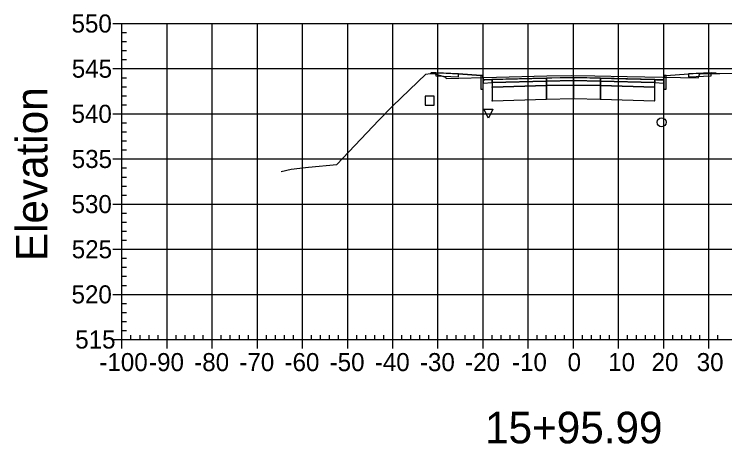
# Model space of a CAD drawing. Extents: x 704834 to 709892, y 372981 to 377533.
# Drawn here: x 706906 to 707063.4, y 376297.7 to 376392.9 of the extents above; entities that cross this region are included whole.
import ezdxf

# ---------------------------------------------------------------- set-up
doc = ezdxf.new("R2010")
doc.units = 0
for name, color, linetype in [('1', 7, 'Continuous'), ('10', 7, 'Continuous'), ('13', 7, 'Continuous'), ('14', 7, 'Continuous'), ('57', 7, 'Continuous'), ('60', 7, 'Continuous'), ('Default_Xsect', 7, 'Continuous'), ('Existing', 7, 'Continuous')]:
    doc.layers.add(name, color=color, linetype=linetype)

msp = doc.modelspace()

# ---------------------------------------------------------------- linework, layer by layer
for points in [[(706998.42, 376379.87), (706998.28, 376379.73)], [(706999.42, 376379.91), (706998.42, 376379.87)], [(707009.42, 376379.31), (707004.42, 376379.71)], [(707050.42, 376379.31), (707055.42, 376379.71)], [(707060.42, 376379.91), (707061.42, 376379.87)], [(707061.42, 376379.87), (707061.55, 376379.73)]]:
    msp.add_lwpolyline(points)
for points in [[(707004.42, 376379.71), (706999.42, 376379.91), (706999.42, 376379.25), (707004.42, 376379.04)], [(707009.92, 376378.31), (707009.83, 376379.31), (707009.42, 376379.31), (707009.42, 376376.31), (707009.92, 376376.31)], [(707023.92, 376378.75), (707011.92, 376378.39), (707011.92, 376377.72), (707023.92, 376378.08)], [(707029.92, 376378.87), (707023.92, 376378.75), (707023.92, 376378.08), (707029.92, 376378.2)], [(707029.92, 376378.2), (707035.92, 376378.08), (707035.92, 376378.75), (707029.92, 376378.87)], [(707035.92, 376378.08), (707047.92, 376377.72), (707047.92, 376378.39), (707035.92, 376378.75)], [(707049.92, 376376.31), (707050.42, 376376.31), (707050.42, 376379.31), (707050, 376379.31), (707049.92, 376378.31)], [(707055.42, 376379.04), (707060.42, 376379.24), (707060.42, 376379.91), (707055.42, 376379.71)], [(707011.92, 376378.39), (707009.92, 376378.31), (707009.92, 376377.64), (707011.92, 376377.72)], [(707023.92, 376378.08), (707011.92, 376377.72), (707011.92, 376376.72), (707023.92, 376377.08)], [(707023.92, 376377.08), (707011.92, 376376.72), (707011.92, 376373.72), (707023.92, 376374.08)], [(707023.87, 376378.03), (707023.97, 376378.03), (707023.97, 376378.13), (707023.87, 376378.13)], [(707023.87, 376377.03), (707023.97, 376377.03), (707023.97, 376377.13), (707023.87, 376377.13)], [(707029.92, 376378.2), (707023.92, 376378.08), (707023.92, 376377.08), (707029.92, 376377.2)], [(707029.92, 376377.2), (707023.92, 376377.08), (707023.92, 376374.08), (707029.92, 376374.2)], [(707029.87, 376378.15), (707029.97, 376378.15), (707029.97, 376378.25), (707029.87, 376378.25)], [(707029.87, 376377.15), (707029.97, 376377.15), (707029.97, 376377.25), (707029.87, 376377.25)], [(707029.92, 376377.2), (707035.92, 376377.08), (707035.92, 376378.08), (707029.92, 376378.2)], [(707029.92, 376374.2), (707035.92, 376374.08), (707035.92, 376377.08), (707029.92, 376377.2)], [(707035.87, 376378.03), (707035.97, 376378.03), (707035.97, 376378.13), (707035.87, 376378.13)], [(707035.87, 376377.03), (707035.97, 376377.03), (707035.97, 376377.13), (707035.87, 376377.13)], [(707035.92, 376377.08), (707047.92, 376376.72), (707047.92, 376377.72), (707035.92, 376378.08)], [(707035.92, 376374.08), (707047.92, 376373.72), (707047.92, 376376.72), (707035.92, 376377.08)], [(707047.92, 376377.72), (707049.92, 376377.64), (707049.92, 376378.31), (707047.92, 376378.39)], [(707011.87, 376376.67), (707011.97, 376376.67), (707011.97, 376376.77), (707011.87, 376376.77)], [(707047.87, 376376.67), (707047.97, 376376.67), (707047.97, 376376.77), (707047.87, 376376.77)], [(707011.87, 376373.67), (707011.97, 376373.67), (707011.97, 376373.77), (707011.87, 376373.77)], [(707023.87, 376374.03), (707023.97, 376374.03), (707023.97, 376374.13), (707023.87, 376374.13)], [(707029.87, 376374.15), (707029.97, 376374.15), (707029.97, 376374.25), (707029.87, 376374.25)], [(707035.87, 376374.03), (707035.97, 376374.03), (707035.97, 376374.13), (707035.87, 376374.13)], [(707047.87, 376373.67), (707047.97, 376373.67), (707047.97, 376373.77), (707047.87, 376373.77)]]:
    msp.add_lwpolyline(points, close=True)
at = {"layer": '1'}
msp.add_lwpolyline([(707011.09, 376369.88), (707010.09, 376371.88), (707012.09, 376371.88)], close=True, dxfattribs=at)
at = {"layer": '10'}
msp.add_lwpolyline([(706997.04, 376372.71), (706999.04, 376372.71), (706999.04, 376374.71), (706997.04, 376374.71)], close=True, dxfattribs=at)
at = {"layer": '13'}
msp.add_circle((707049.43, 376368.94), 1, dxfattribs=at)
at = {"layer": '14'}
for points in [[(706998.28, 376379.73), (706998.28, 376379.78), (706998.28, 376379.73), (706998.23, 376379.73), (706998.28, 376379.73), (706998.28, 376379.68), (706998.28, 376379.73), (706998.33, 376379.73)], [(707029.92, 376378.87), (707029.92, 376378.92), (707029.92, 376378.87), (707029.87, 376378.87), (707029.92, 376378.87), (707029.92, 376378.82), (707029.92, 376378.87), (707029.97, 376378.87)], [(707061.55, 376379.73), (707061.55, 376379.78), (707061.55, 376379.73), (707061.5, 376379.73), (707061.55, 376379.73), (707061.55, 376379.68), (707061.55, 376379.73), (707061.6, 376379.73)], [(707011.92, 376378.39), (707011.92, 376378.44), (707011.92, 376378.39), (707011.87, 376378.39), (707011.92, 376378.39), (707011.92, 376378.34), (707011.92, 376378.39), (707011.97, 376378.39)], [(707047.92, 376378.39), (707047.92, 376378.44), (707047.92, 376378.39), (707047.87, 376378.39), (707047.92, 376378.39), (707047.92, 376378.34), (707047.92, 376378.39), (707047.97, 376378.39)]]:
    msp.add_lwpolyline(points, dxfattribs=at)
at = {"layer": '57'}
for p, q in [((706927.91, 376390.82), (706929.91, 376390.82)), ((706929.91, 376390.82), (707129.91, 376390.82)), ((706929.91, 376320.82), (706929.91, 376390.82)), ((706929.91, 376320.82), (706929.91, 376390.82)), ((706939.91, 376320.82), (706939.91, 376390.82)), ((706949.91, 376320.82), (706949.91, 376390.82)), ((706959.91, 376320.82), (706959.91, 376390.82)), ((706969.91, 376320.82), (706969.91, 376390.82)), ((706979.91, 376320.82), (706979.91, 376390.82)), ((706989.91, 376320.82), (706989.91, 376390.82)), ((706999.91, 376320.82), (706999.91, 376390.82)), ((707009.91, 376320.82), (707009.91, 376390.82)), ((707019.91, 376320.82), (707019.91, 376390.82)), ((707029.91, 376320.82), (707029.91, 376390.82)), ((707039.91, 376320.82), (707039.91, 376390.82)), ((707049.91, 376320.82), (707049.91, 376390.82)), ((707059.91, 376320.82), (707059.91, 376390.82)), ((706929.91, 376388.82), (706930.91, 376388.82)), ((706929.91, 376386.82), (706930.91, 376386.82)), ((706929.91, 376384.82), (706930.91, 376384.82)), ((706929.91, 376382.82), (706930.91, 376382.82)), ((706927.91, 376380.82), (706929.91, 376380.82)), ((706929.91, 376380.82), (707129.91, 376380.82)), ((706929.91, 376378.82), (706930.91, 376378.82)), ((706929.91, 376376.82), (706930.91, 376376.82)), ((706929.91, 376374.82), (706930.91, 376374.82)), ((706929.91, 376372.82), (706930.91, 376372.82)), ((706927.91, 376370.82), (706929.91, 376370.82)), ((706929.91, 376370.82), (707129.91, 376370.82)), ((706929.91, 376368.82), (706930.91, 376368.82)), ((706929.91, 376366.82), (706930.91, 376366.82)), ((706929.91, 376364.82), (706930.91, 376364.82)), ((706929.91, 376362.82), (706930.91, 376362.82)), ((706927.91, 376360.82), (706929.91, 376360.82)), ((706929.91, 376360.82), (707129.91, 376360.82)), ((706929.91, 376358.82), (706930.91, 376358.82)), ((706929.91, 376356.82), (706930.91, 376356.82)), ((706929.91, 376354.82), (706930.91, 376354.82)), ((706929.91, 376352.82), (706930.91, 376352.82)), ((706927.91, 376350.82), (706929.91, 376350.82)), ((706929.91, 376350.82), (707129.91, 376350.82)), ((706929.91, 376348.82), (706930.91, 376348.82)), ((706929.91, 376346.82), (706930.91, 376346.82)), ((706929.91, 376344.82), (706930.91, 376344.82)), ((706929.91, 376342.82), (706930.91, 376342.82)), ((706927.91, 376340.82), (706929.91, 376340.82)), ((706929.91, 376340.82), (707129.91, 376340.82)), ((706929.91, 376338.82), (706930.91, 376338.82)), ((706929.91, 376336.82), (706930.91, 376336.82)), ((706929.91, 376334.82), (706930.91, 376334.82)), ((706929.91, 376332.82), (706930.91, 376332.82)), ((706927.91, 376330.82), (706929.91, 376330.82)), ((706929.91, 376330.82), (707129.91, 376330.82)), ((706929.91, 376328.82), (706930.91, 376328.82)), ((706929.91, 376326.82), (706930.91, 376326.82)), ((706929.91, 376324.82), (706930.91, 376324.82)), ((706929.91, 376322.82), (706930.91, 376322.82)), ((706931.91, 376320.82), (706931.91, 376321.82)), ((706933.91, 376320.82), (706933.91, 376321.82)), ((706935.91, 376320.82), (706935.91, 376321.82)), ((706937.91, 376320.82), (706937.91, 376321.82)), ((706941.91, 376320.82), (706941.91, 376321.82)), ((706943.91, 376320.82), (706943.91, 376321.82)), ((706945.91, 376320.82), (706945.91, 376321.82)), ((706947.91, 376320.82), (706947.91, 376321.82)), ((706951.91, 376320.82), (706951.91, 376321.82)), ((706953.91, 376320.82), (706953.91, 376321.82)), ((706955.91, 376320.82), (706955.91, 376321.82)), ((706957.91, 376320.82), (706957.91, 376321.82)), ((706961.91, 376320.82), (706961.91, 376321.82)), ((706963.91, 376320.82), (706963.91, 376321.82)), ((706965.91, 376320.82), (706965.91, 376321.82)), ((706967.91, 376320.82), (706967.91, 376321.82)), ((706971.91, 376320.82), (706971.91, 376321.82)), ((706973.91, 376320.82), (706973.91, 376321.82)), ((706975.91, 376320.82), (706975.91, 376321.82)), ((706977.91, 376320.82), (706977.91, 376321.82)), ((706981.91, 376320.82), (706981.91, 376321.82)), ((706983.91, 376320.82), (706983.91, 376321.82)), ((706985.91, 376320.82), (706985.91, 376321.82)), ((706987.91, 376320.82), (706987.91, 376321.82)), ((706991.91, 376320.82), (706991.91, 376321.82)), ((706993.91, 376320.82), (706993.91, 376321.82)), ((706995.91, 376320.82), (706995.91, 376321.82)), ((706997.91, 376320.82), (706997.91, 376321.82)), ((707001.91, 376320.82), (707001.91, 376321.82)), ((707003.91, 376320.82), (707003.91, 376321.82)), ((707005.91, 376320.82), (707005.91, 376321.82)), ((707007.91, 376320.82), (707007.91, 376321.82)), ((707011.91, 376320.82), (707011.91, 376321.82)), ((707013.91, 376320.82), (707013.91, 376321.82)), ((707015.91, 376320.82), (707015.91, 376321.82)), ((707017.91, 376320.82), (707017.91, 376321.82)), ((707021.91, 376320.82), (707021.91, 376321.82)), ((707023.91, 376320.82), (707023.91, 376321.82)), ((707025.91, 376320.82), (707025.91, 376321.82)), ((707027.91, 376320.82), (707027.91, 376321.82)), ((707031.91, 376320.82), (707031.91, 376321.82)), ((707033.91, 376320.82), (707033.91, 376321.82)), ((707035.91, 376320.82), (707035.91, 376321.82)), ((707037.91, 376320.82), (707037.91, 376321.82)), ((707041.91, 376320.82), (707041.91, 376321.82)), ((707043.91, 376320.82), (707043.91, 376321.82)), ((707045.91, 376320.82), (707045.91, 376321.82)), ((707047.91, 376320.82), (707047.91, 376321.82)), ((707051.91, 376320.82), (707051.91, 376321.82)), ((707053.91, 376320.82), (707053.91, 376321.82)), ((707055.91, 376320.82), (707055.91, 376321.82)), ((707057.91, 376320.82), (707057.91, 376321.82)), ((707061.91, 376320.82), (707061.91, 376321.82)), ((706927.91, 376320.82), (706929.91, 376320.82)), ((706929.91, 376320.82), (707129.91, 376320.82)), ((706929.91, 376320.82), (707129.91, 376320.82)), ((706929.91, 376318.82), (706929.91, 376320.82)), ((706939.91, 376318.82), (706939.91, 376320.82)), ((706949.91, 376318.82), (706949.91, 376320.82)), ((706959.91, 376318.82), (706959.91, 376320.82)), ((706969.91, 376318.82), (706969.91, 376320.82)), ((706979.91, 376318.82), (706979.91, 376320.82)), ((706989.91, 376318.82), (706989.91, 376320.82)), ((706999.91, 376318.82), (706999.91, 376320.82)), ((707009.91, 376318.82), (707009.91, 376320.82)), ((707019.91, 376318.82), (707019.91, 376320.82)), ((707029.91, 376318.82), (707029.91, 376320.82)), ((707039.91, 376318.82), (707039.91, 376320.82)), ((707049.91, 376318.82), (707049.91, 376320.82)), ((707059.91, 376318.82), (707059.91, 376320.82))]:
    msp.add_line(p, q, dxfattribs=at)
at = {"layer": 'Default_Xsect'}
msp.add_lwpolyline([(706998.28, 376379.73), (706998.4, 376379.85), (706998.42, 376379.87), (706998.61, 376379.88), (706999.42, 376379.91), (707000.39, 376379.87), (707004.42, 376379.71), (707005.39, 376379.63), (707009.42, 376379.31), (707009.5, 376379.31), (707009.83, 376379.31), (707009.85, 376379.12), (707009.92, 376378.31), (707010.31, 376378.33), (707011.92, 376378.39), (707014.29, 376378.46), (707023.92, 376378.75), (707025.11, 376378.77), (707029.92, 376378.87), (707031.11, 376378.84), (707035.92, 376378.75), (707038.33, 376378.67), (707047.92, 376378.39), (707048.32, 376378.37), (707049.92, 376378.31), (707049.93, 376378.51), (707050, 376379.31), (707050.08, 376379.31), (707050.42, 376379.31), (707051.43, 376379.39), (707055.42, 376379.71), (707056.43, 376379.75), (707060.42, 376379.91), (707060.62, 376379.9), (707061.42, 376379.87), (707061.43, 376379.85), (707061.55, 376379.73)], dxfattribs=at)
at = {"layer": 'Existing'}
msp.add_lwpolyline([(706965.15, 376358.03), (706967.36, 376358.53), (706971.23, 376359), (706977.49, 376359.6), (706986.84, 376369.44), (706989.9, 376372.58), (706997.21, 376379.59), (706998.17, 376379.73), (706999.04, 376379.75), (707001.58, 376378.92), (707001.72, 376378.65), (707024.05, 376379.2), (707029.59, 376379.34), (707034.63, 376379.22), (707041.81, 376379.09), (707057.53, 376378.78), (707057.8, 376379.38), (707057.98, 376379.72), (707058.62, 376379.72), (707061.89, 376379.73), (707062.31, 376379.75), (707067.3, 376379.83)], dxfattribs=at)

# ---------------------------------------------------------------- texts
at = {"layer": '1'}
msp.add_text('15+95.99', height=7, dxfattribs=at).set_placement((707010.34, 376297.82))
at = {"layer": '14'}
for p in [(706999.38, 376379.86), (706999.38, 376379.2), (707004.38, 376378.99), (707055.38, 376378.99), (707060.38, 376379.86), (707060.38, 376379.19)]:
    msp.add_text('+', height=0.1, dxfattribs=at).set_placement(p)
at = {"layer": '57'}
for s, p in [('550', (706918.74, 376388.82)), ('545', (706918.79, 376378.82)), ('540', (706918.74, 376368.82)), ('535', (706918.79, 376358.82)), ('530', (706918.74, 376348.82)), ('525', (706918.79, 376338.82)), ('520', (706918.74, 376328.82)), ('515', (706919.56, 376318.82)), ('-100', (706924.9, 376313.82)), ('-90', (706935.91, 376313.82)), ('-80', (706945.91, 376313.82)), ('-70', (706955.91, 376313.82)), ('-60', (706965.91, 376313.82)), ('-50', (706975.91, 376313.82)), ('-40', (706985.91, 376313.82)), ('-30', (706995.91, 376313.82)), ('-20', (707005.91, 376313.82)), ('-10', (707016.3, 376313.82)), ('0', (707028.62, 376313.82)), ('10', (707037.61, 376313.82)), ('20', (707047.22, 376313.82)), ('30', (707057.22, 376313.82))]:
    msp.add_text(s, height=4, dxfattribs=at).set_placement(p)
at = {"layer": '60'}
msp.add_text('Elevation', height=7, rotation=90, dxfattribs=at).set_placement((706913.41, 376338.18))

doc.saveas('drawing.dxf')
